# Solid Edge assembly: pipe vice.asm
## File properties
Author: Deepak Maini
Template: normal.asm
Last saved by: Robert a Rhodes jr
Revision: 5
Application: Solid Edge
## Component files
base.par
Screw.par
moveable jaw.par
handle.par
handle screw.par
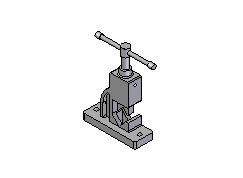
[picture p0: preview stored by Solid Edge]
